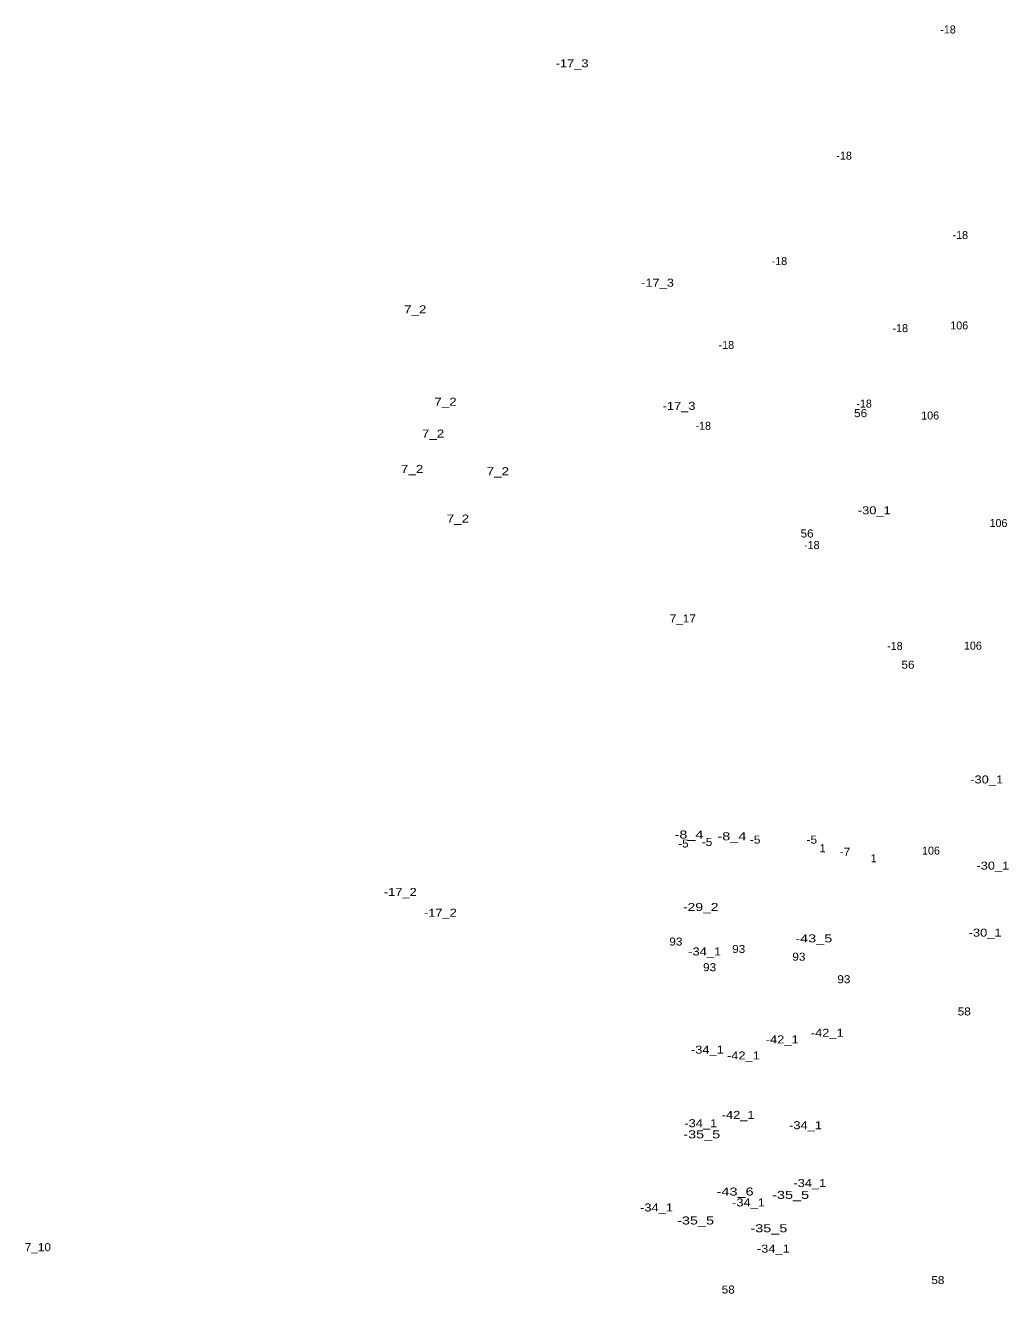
# Model space of a CAD drawing. Extents: x -663705 to -661666, y -1002081 to -999269.
# Drawn here: x -663388 to -662897, y -999903 to -999269 of the extents above; entities that cross this region are included whole.
import ezdxf
from ezdxf.enums import TextEntityAlignment as Align

# ---------------------------------------------------------------- set-up
doc = ezdxf.new("R2010")
doc.units = 0
doc.header["$LTSCALE"] = 1.6
doc.layers.add('24', color=7, linetype='Continuous')

msp = doc.modelspace()

# ---------------------------------------------------------------- texts
at = {"layer": '24'}
for s, p in [('-18', (-662927.111, -999273.16)), ('-18', (-662979.01, -999336.2)), ('-18', (-662920.961, -999375.85)), ('-18', (-663011.311, -999388.87)), ('-18', (-662950.951, -999422.39)), ('106', (-662921.481, -999421.04)), ('-18', (-663037.841, -999430.79)), ('-18', (-662969.02, -999460.08)), ('106', (-662936.02, -999466.04)), ('-18', (-663049.37, -999471.17)), ('106', (-662901.9, -999519.76)), ('-18', (-662995.16, -999530.78)), ('-18', (-662953.64, -999581.17)), ('106', (-662914.691, -999581.05)), ('1', (-662989.802, -999682.25)), ('106', (-662935.63, -999683.45)), ('1', (-662964.232, -999687.25))]:
    msp.add_text(s, height=4, dxfattribs=at).set_placement(p, align=Align.CENTER)
for s, width, p in [('-17_3', 1.2, (-663114.92, -999290.07)), ('-17_3', 1.2, (-663072.24, -999399.69)), ('7_2', 1.25, (-663193.26, -999413)), ('7_2', 1.25, (-663178.14, -999459.16)), ('-17_3', 1.2, (-663061.48, -999461.22)), ('56', 1.1, (-662970.77, -999464.86)), ('7_2', 1.25, (-663184.34, -999475.06)), ('7_2', 1.25, (-663194.809, -999492.71)), ('7_2', 1.25, (-663151.959, -999493.87)), ('-30_1', 1.2, (-662963.929, -999513.4)), ('7_2', 1.25, (-663171.929, -999517.53)), ('56', 1.1, (-662997.52, -999524.98)), ('7_17', 1.1, (-663059.61, -999567.45)), ('56', 1.1, (-662947.12, -999590.53)), ('-30_1', 1.2, (-662907.79, -999647.88)), ('-8_4', 1.35, (-663056.5, -999675.4)), ('-8_4', 1.35, (-663035.08, -999676.27)), ('-5', 1.1, (-663023.43, -999677.95)), ('-5', 1.1, (-662995.13, -999677.95)), ('-5', 1.1, (-663059.3, -999679.89)), ('-5', 1.1, (-663047.47, -999679.11)), ('-7', 1.1, (-662978.571, -999684.02)), ('-30_1', 1.2, (-662904.72, -999690.96)), ('-17_2', 1.2, (-663200.71, -999704.1)), ('-17_2', 1.2, (-663180.71, -999714.48)), ('-29_2', 1.3, (-663050.64, -999711.6)), ('93', 1.1, (-663063.07, -999728.88)), ('-43_5', 1.35, (-662994.15, -999727.3)), ('-30_1', 1.2, (-662908.559, -999724.42)), ('-34_1', 1.2, (-663048.679, -999733.83)), ('93', 1.1, (-663031.66, -999732.57)), ('93', 1.1, (-663046.2, -999741.68)), ('93', 1.1, (-663001.61, -999736.45)), ('93', 1.1, (-662979.13, -999747.7)), ('58', 1.1, (-662919, -999763.8)), ('-42_1', 1.2, (-663009.949, -999777.76)), ('-42_1', 1.2, (-662987.459, -999774.47)), ('-34_1', 1.2, (-663047.319, -999782.89)), ('-42_1', 1.2, (-663029.329, -999785.81)), ('-42_1', 1.2, (-663031.949, -999815.48)), ('-34_1', 1.2, (-663050.62, -999819.66)), ('-34_1', 1.2, (-662998.28, -999820.63)), ('-35_5', 1.35, (-663050.13, -999825.2)), ('-34_1', 1.2, (-662996.14, -999849.53)), ('-43_6', 1.35, (-663033.46, -999853.79)), ('-35_5', 1.35, (-663005.74, -999855.45)), ('-34_1', 1.2, (-663072.72, -999861.75)), ('-34_1', 1.2, (-663026.77, -999859.23)), ('-35_5', 1.35, (-663053.23, -999868.25)), ('-35_5', 1.35, (-663016.59, -999872.13)), ('7_10', 1.1, (-663381.78, -999881.58)), ('-34_1', 1.2, (-663014.37, -999882.31)), ('58', 1.1, (-662932.179, -999898.01)), ('58', 1.1, (-663036.91, -999902.74))]:
    msp.add_text(s, height=4, dxfattribs=dict(at, width=width)).set_placement(p, align=Align.CENTER)

doc.saveas('drawing.dxf')
